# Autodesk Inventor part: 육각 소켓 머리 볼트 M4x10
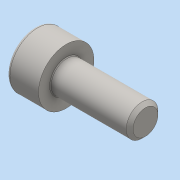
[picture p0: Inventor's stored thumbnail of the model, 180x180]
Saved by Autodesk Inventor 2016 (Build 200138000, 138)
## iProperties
Created: 2024-09
Part Number: 육각 소켓 머리 볼트 M4x10
Material: 일반
Description: 6각머리 태핑 나사
Document SubType Name: Modeling
Designer: pc-7
Density: 1 g/cm^3
Appearance: 기본값
Author: jhkim
Sending System: Autodesk Inventor 2025
Preprocessor: ST-DEVELOPER v20
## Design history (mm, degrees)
node "육각 소켓 머리 볼트 M4x101"
node "솔리드1"
body "Solid1"
